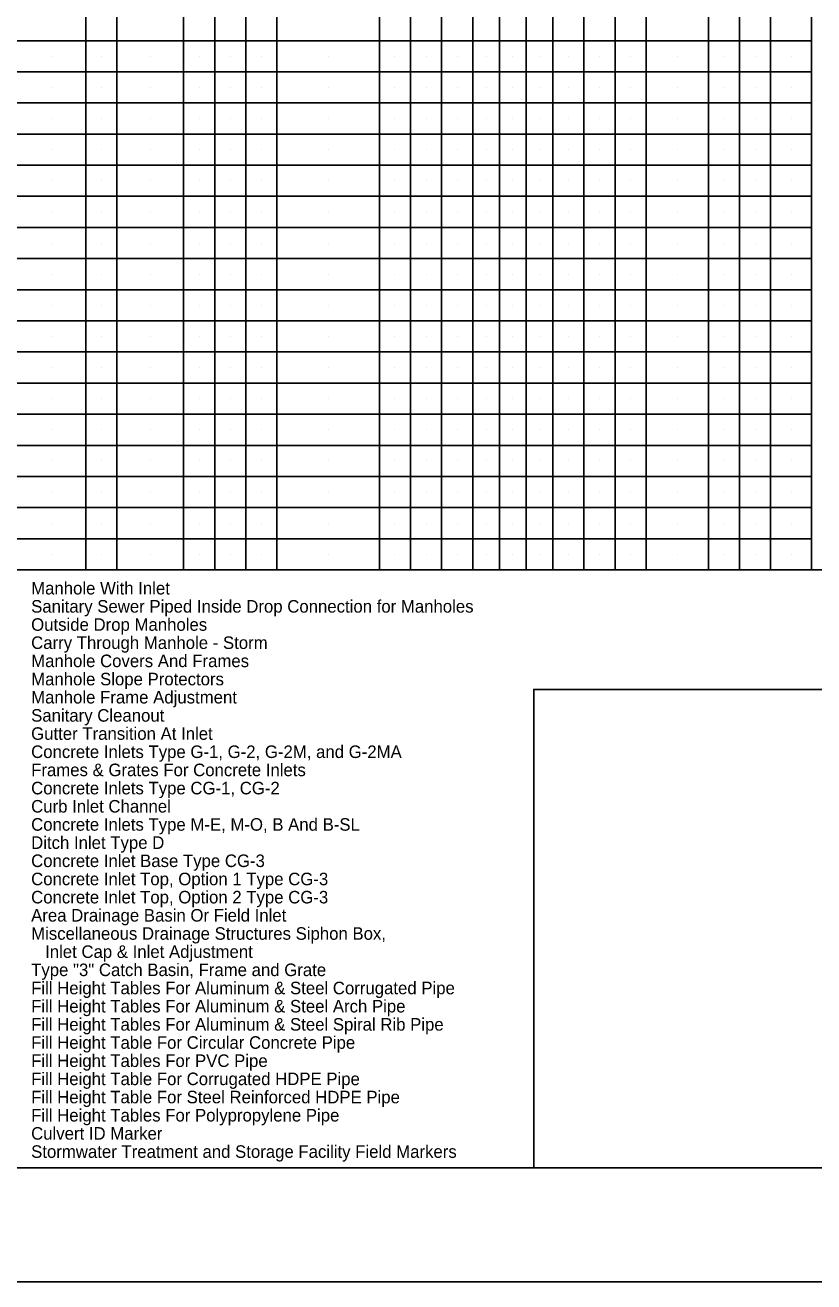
# Model space of a CAD drawing. Extents: x 0 to 1.42, y 0 to 0.92.
# Drawn here: x 0.7723 to 1.0608, y 0 to 0.4596 of the extents above; entities that cross this region are included whole.
import ezdxf

# ---------------------------------------------------------------- set-up
doc = ezdxf.new("R2010")
doc.units = 0
for name, color, linetype in [('#plot_shape', 7, 'Continuous'), ('P_ODOT_PLAN_Border', 7, 'Continuous'), ('P_ODOT_PLAN_General', 7, 'Continuous'), ('P_RDWY_PLAN_NotesTx', 7, 'Continuous')]:
    doc.layers.add(name, color=color, linetype=linetype)

msp = doc.modelspace()

# ---------------------------------------------------------------- linework, layer by layer
at = {"layer": '#plot_shape'}
msp.add_lwpolyline([(0, 0), (1.41667, 0), (1.41667, 0.91667), (0, 0.91667)], close=True, dxfattribs=at)
at = {"layer": 'P_ODOT_PLAN_Border'}
msp.add_lwpolyline([(0.0625, 0.04167), (1.39583, 0.04167), (1.39583, 0.875), (0.0625, 0.875)], close=True, dxfattribs=at)
msp.add_lwpolyline([(1.39587, 0.21667), (0.95837, 0.21667), (0.95837, 0.04167)], dxfattribs=at)
at = {"layer": 'P_ODOT_PLAN_General'}
for p, q in [((1.06002, 0.26037), (1.06002, 0.875)), ((0.93608, 0.26037), (0.93608, 0.86362)), ((0.96534, 0.26037), (0.96534, 0.86362)), ((0.97673, 0.26037), (0.97673, 0.85305)), ((0.98811, 0.26037), (0.98811, 0.85305)), ((0.99949, 0.26037), (0.99949, 0.85305)), ((1.02226, 0.26037), (1.02226, 0.85305)), ((1.03364, 0.26037), (1.03364, 0.85305)), ((1.04502, 0.26037), (1.04502, 0.85305)), ((0.86443, 0.26037), (0.86443, 0.83191)), ((0.94583, 0.26037), (0.94583, 0.82887)), ((0.95559, 0.26037), (0.95559, 0.82887)), ((0.80589, 0.26037), (0.80589, 0.82134)), ((0.84167, 0.26037), (0.84167, 0.82134)), ((0.90193, 0.26037), (0.90193, 0.82134)), ((0.91331, 0.26037), (0.91331, 0.82134)), ((0.79451, 0.26037), (0.79451, 0.81159)), ((0.83028, 0.26037), (0.83028, 0.81159)), ((0.85305, 0.26037), (0.85305, 0.81159)), ((0.92469, 0.26037), (0.92469, 0.81159)), ((1.06002, 0.45387), (0.55518, 0.45387)), ((0.78232, 0.44818), (0.78232, 0.44818)), ((0.8002, 0.44818), (0.8002, 0.44818)), ((0.81809, 0.44818), (0.81809, 0.44818)), ((0.83597, 0.44818), (0.83597, 0.44818)), ((0.84736, 0.44818), (0.84736, 0.44818)), ((0.85874, 0.44818), (0.85874, 0.44818)), ((0.88318, 0.44818), (0.88318, 0.44818)), ((0.90762, 0.44818), (0.90762, 0.44818)), ((0.919, 0.44818), (0.919, 0.44818)), ((0.93038, 0.44818), (0.93038, 0.44818)), ((0.94095, 0.44818), (0.94095, 0.44818)), ((0.95071, 0.44818), (0.95071, 0.44818)), ((0.96047, 0.44818), (0.96047, 0.44818)), ((0.97103, 0.44818), (0.97103, 0.44818)), ((0.98242, 0.44818), (0.98242, 0.44818)), ((0.9938, 0.44818), (0.9938, 0.44818)), ((1.01087, 0.44818), (1.01087, 0.44818)), ((1.02795, 0.44818), (1.02795, 0.44818)), ((1.03933, 0.44818), (1.03933, 0.44818)), ((1.05252, 0.44818), (1.05252, 0.44818)), ((1.06002, 0.44248), (0.55518, 0.44248)), ((0.78232, 0.43679), (0.78232, 0.43679)), ((0.8002, 0.43679), (0.8002, 0.43679)), ((0.81809, 0.43679), (0.81809, 0.43679)), ((0.83597, 0.43679), (0.83597, 0.43679)), ((0.84736, 0.43679), (0.84736, 0.43679)), ((0.85874, 0.43679), (0.85874, 0.43679)), ((0.88318, 0.43679), (0.88318, 0.43679)), ((0.90762, 0.43679), (0.90762, 0.43679)), ((0.919, 0.43679), (0.919, 0.43679)), ((0.93038, 0.43679), (0.93038, 0.43679)), ((0.94095, 0.43679), (0.94095, 0.43679)), ((0.95071, 0.43679), (0.95071, 0.43679)), ((0.96047, 0.43679), (0.96047, 0.43679)), ((0.97103, 0.43679), (0.97103, 0.43679)), ((0.98242, 0.43679), (0.98242, 0.43679)), ((0.9938, 0.43679), (0.9938, 0.43679)), ((1.01087, 0.43679), (1.01087, 0.43679)), ((1.02795, 0.43679), (1.02795, 0.43679)), ((1.03933, 0.43679), (1.03933, 0.43679)), ((1.05252, 0.43679), (1.05252, 0.43679)), ((1.06002, 0.4311), (0.55518, 0.4311)), ((0.78232, 0.42541), (0.78232, 0.42541)), ((0.8002, 0.42541), (0.8002, 0.42541)), ((0.81809, 0.42541), (0.81809, 0.42541)), ((0.83597, 0.42541), (0.83597, 0.42541)), ((0.84736, 0.42541), (0.84736, 0.42541)), ((0.85874, 0.42541), (0.85874, 0.42541)), ((0.88318, 0.42541), (0.88318, 0.42541)), ((0.90762, 0.42541), (0.90762, 0.42541)), ((0.919, 0.42541), (0.919, 0.42541)), ((0.93038, 0.42541), (0.93038, 0.42541)), ((0.94095, 0.42541), (0.94095, 0.42541)), ((0.95071, 0.42541), (0.95071, 0.42541)), ((0.96047, 0.42541), (0.96047, 0.42541)), ((0.97103, 0.42541), (0.97103, 0.42541)), ((0.98242, 0.42541), (0.98242, 0.42541)), ((0.9938, 0.42541), (0.9938, 0.42541)), ((1.01087, 0.42541), (1.01087, 0.42541)), ((1.02795, 0.42541), (1.02795, 0.42541)), ((1.03933, 0.42541), (1.03933, 0.42541)), ((1.05252, 0.42541), (1.05252, 0.42541)), ((1.06002, 0.41972), (0.55518, 0.41972)), ((0.78232, 0.41403), (0.78232, 0.41403)), ((0.8002, 0.41403), (0.8002, 0.41403)), ((0.81809, 0.41403), (0.81809, 0.41403)), ((0.83597, 0.41403), (0.83597, 0.41403)), ((0.84736, 0.41403), (0.84736, 0.41403)), ((0.85874, 0.41403), (0.85874, 0.41403)), ((0.88318, 0.41403), (0.88318, 0.41403)), ((0.90762, 0.41403), (0.90762, 0.41403)), ((0.919, 0.41403), (0.919, 0.41403)), ((0.93038, 0.41403), (0.93038, 0.41403)), ((0.94095, 0.41403), (0.94095, 0.41403)), ((0.95071, 0.41403), (0.95071, 0.41403)), ((0.96047, 0.41403), (0.96047, 0.41403)), ((0.97103, 0.41403), (0.97103, 0.41403)), ((0.98242, 0.41403), (0.98242, 0.41403)), ((0.9938, 0.41403), (0.9938, 0.41403)), ((1.01087, 0.41403), (1.01087, 0.41403)), ((1.02795, 0.41403), (1.02795, 0.41403)), ((1.03933, 0.41403), (1.03933, 0.41403)), ((1.05252, 0.41403), (1.05252, 0.41403)), ((1.06002, 0.40834), (0.55518, 0.40834)), ((0.78232, 0.40265), (0.78232, 0.40265)), ((0.8002, 0.40265), (0.8002, 0.40265)), ((0.81809, 0.40265), (0.81809, 0.40265)), ((0.83597, 0.40265), (0.83597, 0.40265)), ((0.84736, 0.40265), (0.84736, 0.40265)), ((0.85874, 0.40265), (0.85874, 0.40265)), ((0.88318, 0.40265), (0.88318, 0.40265)), ((0.90762, 0.40265), (0.90762, 0.40265)), ((0.919, 0.40265), (0.919, 0.40265)), ((0.93038, 0.40265), (0.93038, 0.40265)), ((0.94095, 0.40265), (0.94095, 0.40265)), ((0.95071, 0.40265), (0.95071, 0.40265)), ((0.96047, 0.40265), (0.96047, 0.40265)), ((0.97103, 0.40265), (0.97103, 0.40265)), ((0.98242, 0.40265), (0.98242, 0.40265)), ((0.9938, 0.40265), (0.9938, 0.40265)), ((1.01087, 0.40265), (1.01087, 0.40265)), ((1.02795, 0.40265), (1.02795, 0.40265)), ((1.03933, 0.40265), (1.03933, 0.40265)), ((1.05252, 0.40265), (1.05252, 0.40265)), ((1.06002, 0.39696), (0.55518, 0.39696)), ((0.78232, 0.39127), (0.78232, 0.39127)), ((0.8002, 0.39127), (0.8002, 0.39127)), ((0.81809, 0.39127), (0.81809, 0.39127)), ((0.83597, 0.39127), (0.83597, 0.39127)), ((0.84736, 0.39127), (0.84736, 0.39127)), ((0.85874, 0.39127), (0.85874, 0.39127)), ((0.88318, 0.39127), (0.88318, 0.39127)), ((0.90762, 0.39127), (0.90762, 0.39127)), ((0.919, 0.39127), (0.919, 0.39127)), ((0.93038, 0.39127), (0.93038, 0.39127)), ((0.94095, 0.39127), (0.94095, 0.39127)), ((0.95071, 0.39127), (0.95071, 0.39127)), ((0.96047, 0.39127), (0.96047, 0.39127)), ((0.97103, 0.39127), (0.97103, 0.39127)), ((0.98242, 0.39127), (0.98242, 0.39127)), ((0.9938, 0.39127), (0.9938, 0.39127)), ((1.01087, 0.39127), (1.01087, 0.39127)), ((1.02795, 0.39127), (1.02795, 0.39127)), ((1.03933, 0.39127), (1.03933, 0.39127)), ((1.05252, 0.39127), (1.05252, 0.39127)), ((1.06002, 0.38557), (0.55518, 0.38557)), ((0.78232, 0.37988), (0.78232, 0.37988)), ((0.8002, 0.37988), (0.8002, 0.37988)), ((0.81809, 0.37988), (0.81809, 0.37988)), ((0.83597, 0.37988), (0.83597, 0.37988)), ((0.84736, 0.37988), (0.84736, 0.37988)), ((0.85874, 0.37988), (0.85874, 0.37988)), ((0.88318, 0.37988), (0.88318, 0.37988)), ((0.90762, 0.37988), (0.90762, 0.37988)), ((0.919, 0.37988), (0.919, 0.37988)), ((0.93038, 0.37988), (0.93038, 0.37988)), ((0.94095, 0.37988), (0.94095, 0.37988)), ((0.95071, 0.37988), (0.95071, 0.37988)), ((0.96047, 0.37988), (0.96047, 0.37988)), ((0.97103, 0.37988), (0.97103, 0.37988)), ((0.98242, 0.37988), (0.98242, 0.37988)), ((0.9938, 0.37988), (0.9938, 0.37988)), ((1.01087, 0.37988), (1.01087, 0.37988)), ((1.02795, 0.37988), (1.02795, 0.37988)), ((1.03933, 0.37988), (1.03933, 0.37988)), ((1.05252, 0.37988), (1.05252, 0.37988)), ((1.06002, 0.37419), (0.55518, 0.37419)), ((0.78232, 0.3685), (0.78232, 0.3685)), ((0.8002, 0.3685), (0.8002, 0.3685)), ((0.81809, 0.3685), (0.81809, 0.3685)), ((0.83597, 0.3685), (0.83597, 0.3685)), ((0.84736, 0.3685), (0.84736, 0.3685)), ((0.85874, 0.3685), (0.85874, 0.3685)), ((0.88318, 0.3685), (0.88318, 0.3685)), ((0.90762, 0.3685), (0.90762, 0.3685)), ((0.919, 0.3685), (0.919, 0.3685)), ((0.93038, 0.3685), (0.93038, 0.3685)), ((0.94095, 0.3685), (0.94095, 0.3685)), ((0.95071, 0.3685), (0.95071, 0.3685)), ((0.96047, 0.3685), (0.96047, 0.3685)), ((0.97103, 0.3685), (0.97103, 0.3685)), ((0.98242, 0.3685), (0.98242, 0.3685)), ((0.9938, 0.3685), (0.9938, 0.3685)), ((1.01087, 0.3685), (1.01087, 0.3685)), ((1.02795, 0.3685), (1.02795, 0.3685)), ((1.03933, 0.3685), (1.03933, 0.3685)), ((1.05252, 0.3685), (1.05252, 0.3685)), ((1.06002, 0.36281), (0.55518, 0.36281)), ((0.78232, 0.35712), (0.78232, 0.35712)), ((0.8002, 0.35712), (0.8002, 0.35712)), ((0.81809, 0.35712), (0.81809, 0.35712)), ((0.83597, 0.35712), (0.83597, 0.35712)), ((0.84736, 0.35712), (0.84736, 0.35712)), ((0.85874, 0.35712), (0.85874, 0.35712)), ((0.88318, 0.35712), (0.88318, 0.35712)), ((0.90762, 0.35712), (0.90762, 0.35712)), ((0.919, 0.35712), (0.919, 0.35712)), ((0.93038, 0.35712), (0.93038, 0.35712)), ((0.94095, 0.35712), (0.94095, 0.35712)), ((0.95071, 0.35712), (0.95071, 0.35712)), ((0.96047, 0.35712), (0.96047, 0.35712)), ((0.97103, 0.35712), (0.97103, 0.35712)), ((0.98242, 0.35712), (0.98242, 0.35712)), ((0.9938, 0.35712), (0.9938, 0.35712)), ((1.01087, 0.35712), (1.01087, 0.35712)), ((1.02795, 0.35712), (1.02795, 0.35712)), ((1.03933, 0.35712), (1.03933, 0.35712)), ((1.05252, 0.35712), (1.05252, 0.35712)), ((1.06002, 0.35143), (0.55518, 0.35143)), ((0.78232, 0.34574), (0.78232, 0.34574)), ((0.8002, 0.34574), (0.8002, 0.34574)), ((0.81809, 0.34574), (0.81809, 0.34574)), ((0.83597, 0.34574), (0.83597, 0.34574)), ((0.84736, 0.34574), (0.84736, 0.34574)), ((0.85874, 0.34574), (0.85874, 0.34574)), ((0.88318, 0.34574), (0.88318, 0.34574)), ((0.90762, 0.34574), (0.90762, 0.34574)), ((0.919, 0.34574), (0.919, 0.34574)), ((0.93038, 0.34574), (0.93038, 0.34574)), ((0.94095, 0.34574), (0.94095, 0.34574)), ((0.95071, 0.34574), (0.95071, 0.34574)), ((0.96047, 0.34574), (0.96047, 0.34574)), ((0.97103, 0.34574), (0.97103, 0.34574)), ((0.98242, 0.34574), (0.98242, 0.34574)), ((0.9938, 0.34574), (0.9938, 0.34574)), ((1.01087, 0.34574), (1.01087, 0.34574)), ((1.02795, 0.34574), (1.02795, 0.34574)), ((1.03933, 0.34574), (1.03933, 0.34574)), ((1.05252, 0.34574), (1.05252, 0.34574)), ((1.06002, 0.34005), (0.55518, 0.34005)), ((0.78232, 0.33436), (0.78232, 0.33436)), ((0.8002, 0.33436), (0.8002, 0.33436)), ((0.81809, 0.33436), (0.81809, 0.33436)), ((0.83597, 0.33436), (0.83597, 0.33436)), ((0.84736, 0.33436), (0.84736, 0.33436)), ((0.85874, 0.33436), (0.85874, 0.33436)), ((0.88318, 0.33436), (0.88318, 0.33436)), ((0.90762, 0.33436), (0.90762, 0.33436)), ((0.919, 0.33436), (0.919, 0.33436)), ((0.93038, 0.33436), (0.93038, 0.33436)), ((0.94095, 0.33436), (0.94095, 0.33436)), ((0.95071, 0.33436), (0.95071, 0.33436)), ((0.96047, 0.33436), (0.96047, 0.33436)), ((0.97103, 0.33436), (0.97103, 0.33436)), ((0.98242, 0.33436), (0.98242, 0.33436)), ((0.9938, 0.33436), (0.9938, 0.33436)), ((1.01087, 0.33436), (1.01087, 0.33436)), ((1.02795, 0.33436), (1.02795, 0.33436)), ((1.03933, 0.33436), (1.03933, 0.33436)), ((1.05252, 0.33436), (1.05252, 0.33436)), ((1.06002, 0.32866), (0.55518, 0.32866)), ((0.78232, 0.32297), (0.78232, 0.32297)), ((0.8002, 0.32297), (0.8002, 0.32297)), ((0.81809, 0.32297), (0.81809, 0.32297)), ((0.83597, 0.32297), (0.83597, 0.32297)), ((0.84736, 0.32297), (0.84736, 0.32297)), ((0.85874, 0.32297), (0.85874, 0.32297)), ((0.88318, 0.32297), (0.88318, 0.32297)), ((0.90762, 0.32297), (0.90762, 0.32297)), ((0.919, 0.32297), (0.919, 0.32297)), ((0.93038, 0.32297), (0.93038, 0.32297)), ((0.94095, 0.32297), (0.94095, 0.32297)), ((0.95071, 0.32297), (0.95071, 0.32297)), ((0.96047, 0.32297), (0.96047, 0.32297)), ((0.97103, 0.32297), (0.97103, 0.32297)), ((0.98242, 0.32297), (0.98242, 0.32297)), ((0.9938, 0.32297), (0.9938, 0.32297)), ((1.01087, 0.32297), (1.01087, 0.32297)), ((1.02795, 0.32297), (1.02795, 0.32297)), ((1.03933, 0.32297), (1.03933, 0.32297)), ((1.05252, 0.32297), (1.05252, 0.32297)), ((1.06002, 0.31728), (0.55518, 0.31728)), ((0.78232, 0.31159), (0.78232, 0.31159)), ((0.8002, 0.31159), (0.8002, 0.31159)), ((0.81809, 0.31159), (0.81809, 0.31159)), ((0.83597, 0.31159), (0.83597, 0.31159)), ((0.84736, 0.31159), (0.84736, 0.31159)), ((0.85874, 0.31159), (0.85874, 0.31159)), ((0.88318, 0.31159), (0.88318, 0.31159)), ((0.90762, 0.31159), (0.90762, 0.31159)), ((0.919, 0.31159), (0.919, 0.31159)), ((0.93038, 0.31159), (0.93038, 0.31159)), ((0.94095, 0.31159), (0.94095, 0.31159)), ((0.95071, 0.31159), (0.95071, 0.31159)), ((0.96047, 0.31159), (0.96047, 0.31159)), ((0.97103, 0.31159), (0.97103, 0.31159)), ((0.98242, 0.31159), (0.98242, 0.31159)), ((0.9938, 0.31159), (0.9938, 0.31159)), ((1.01087, 0.31159), (1.01087, 0.31159)), ((1.02795, 0.31159), (1.02795, 0.31159)), ((1.03933, 0.31159), (1.03933, 0.31159)), ((1.05252, 0.31159), (1.05252, 0.31159)), ((1.06002, 0.3059), (0.55518, 0.3059)), ((0.78232, 0.30021), (0.78232, 0.30021)), ((0.8002, 0.30021), (0.8002, 0.30021)), ((0.81809, 0.30021), (0.81809, 0.30021)), ((0.83597, 0.30021), (0.83597, 0.30021)), ((0.84736, 0.30021), (0.84736, 0.30021)), ((0.85874, 0.30021), (0.85874, 0.30021)), ((0.88318, 0.30021), (0.88318, 0.30021)), ((0.90762, 0.30021), (0.90762, 0.30021)), ((0.919, 0.30021), (0.919, 0.30021)), ((0.93038, 0.30021), (0.93038, 0.30021)), ((0.94095, 0.30021), (0.94095, 0.30021)), ((0.95071, 0.30021), (0.95071, 0.30021)), ((0.96047, 0.30021), (0.96047, 0.30021)), ((0.97103, 0.30021), (0.97103, 0.30021)), ((0.98242, 0.30021), (0.98242, 0.30021)), ((0.9938, 0.30021), (0.9938, 0.30021)), ((1.01087, 0.30021), (1.01087, 0.30021)), ((1.02795, 0.30021), (1.02795, 0.30021)), ((1.03933, 0.30021), (1.03933, 0.30021)), ((1.05252, 0.30021), (1.05252, 0.30021)), ((1.06002, 0.29452), (0.55518, 0.29452)), ((0.78232, 0.28883), (0.78232, 0.28883)), ((0.8002, 0.28883), (0.8002, 0.28883)), ((0.81809, 0.28883), (0.81809, 0.28883)), ((0.83597, 0.28883), (0.83597, 0.28883)), ((0.84736, 0.28883), (0.84736, 0.28883)), ((0.85874, 0.28883), (0.85874, 0.28883)), ((0.88318, 0.28883), (0.88318, 0.28883)), ((0.90762, 0.28883), (0.90762, 0.28883)), ((0.919, 0.28883), (0.919, 0.28883)), ((0.93038, 0.28883), (0.93038, 0.28883)), ((0.94095, 0.28883), (0.94095, 0.28883)), ((0.95071, 0.28883), (0.95071, 0.28883)), ((0.96047, 0.28883), (0.96047, 0.28883)), ((0.97103, 0.28883), (0.97103, 0.28883)), ((0.98242, 0.28883), (0.98242, 0.28883)), ((0.9938, 0.28883), (0.9938, 0.28883)), ((1.01087, 0.28883), (1.01087, 0.28883)), ((1.02795, 0.28883), (1.02795, 0.28883)), ((1.03933, 0.28883), (1.03933, 0.28883)), ((1.05252, 0.28883), (1.05252, 0.28883)), ((1.06002, 0.28314), (0.55518, 0.28314)), ((0.78232, 0.27745), (0.78232, 0.27745)), ((0.8002, 0.27745), (0.8002, 0.27745)), ((0.81809, 0.27745), (0.81809, 0.27745)), ((0.83597, 0.27745), (0.83597, 0.27745)), ((0.84736, 0.27745), (0.84736, 0.27745)), ((0.85874, 0.27745), (0.85874, 0.27745)), ((0.88318, 0.27745), (0.88318, 0.27745)), ((0.90762, 0.27745), (0.90762, 0.27745)), ((0.919, 0.27745), (0.919, 0.27745)), ((0.93038, 0.27745), (0.93038, 0.27745)), ((0.94095, 0.27745), (0.94095, 0.27745)), ((0.95071, 0.27745), (0.95071, 0.27745)), ((0.96047, 0.27745), (0.96047, 0.27745)), ((0.97103, 0.27745), (0.97103, 0.27745)), ((0.98242, 0.27745), (0.98242, 0.27745)), ((0.9938, 0.27745), (0.9938, 0.27745)), ((1.01087, 0.27745), (1.01087, 0.27745)), ((1.02795, 0.27745), (1.02795, 0.27745)), ((1.03933, 0.27745), (1.03933, 0.27745)), ((1.05252, 0.27745), (1.05252, 0.27745)), ((1.06002, 0.27175), (0.55518, 0.27175)), ((0.78232, 0.26606), (0.78232, 0.26606)), ((0.8002, 0.26606), (0.8002, 0.26606)), ((0.81809, 0.26606), (0.81809, 0.26606)), ((0.83597, 0.26606), (0.83597, 0.26606)), ((0.84736, 0.26606), (0.84736, 0.26606)), ((0.85874, 0.26606), (0.85874, 0.26606)), ((0.88318, 0.26606), (0.88318, 0.26606)), ((0.90762, 0.26606), (0.90762, 0.26606)), ((0.919, 0.26606), (0.919, 0.26606)), ((0.93038, 0.26606), (0.93038, 0.26606)), ((0.94095, 0.26606), (0.94095, 0.26606)), ((0.95071, 0.26606), (0.95071, 0.26606)), ((0.96047, 0.26606), (0.96047, 0.26606)), ((0.97103, 0.26606), (0.97103, 0.26606)), ((0.98242, 0.26606), (0.98242, 0.26606)), ((0.9938, 0.26606), (0.9938, 0.26606)), ((1.01087, 0.26606), (1.01087, 0.26606)), ((1.02795, 0.26606), (1.02795, 0.26606)), ((1.03933, 0.26606), (1.03933, 0.26606)), ((1.05252, 0.26606), (1.05252, 0.26606)), ((1.39582, 0.26037), (0.0625, 0.26037)), ((1.39582, 0.26037), (0.0625, 0.26037))]:
    msp.add_line(p, q, dxfattribs=at)

# ---------------------------------------------------------------- texts
at = {"layer": 'P_RDWY_PLAN_NotesTx'}
for s, p in [('Manhole With Inlet', (0.77453, 0.25137)), ('Sanitary Sewer Piped Inside Drop Connection for Manholes', (0.77453, 0.24473)), ('Outside Drop Manholes', (0.77453, 0.23808)), ('Carry Through Manhole - Storm', (0.77453, 0.23144)), ('Manhole Covers And Frames', (0.77453, 0.22479)), ('Manhole Slope Protectors', (0.77453, 0.21814)), ('Manhole Frame Adjustment', (0.77453, 0.2115)), ('Sanitary Cleanout', (0.77453, 0.20485)), ('Gutter Transition At Inlet', (0.77453, 0.19821)), ('Concrete Inlets Type G-1, G-2, G-2M, and G-2MA', (0.77453, 0.19156)), ('Frames & Grates For Concrete Inlets', (0.77453, 0.18492)), ('Concrete Inlets Type CG-1, CG-2', (0.77453, 0.17827)), ('Curb Inlet Channel', (0.77453, 0.17162)), ('Concrete Inlets Type M-E, M-O, B And B-SL', (0.77453, 0.16498)), ('Ditch Inlet Type D', (0.77453, 0.15833)), ('Concrete Inlet Base Type CG-3', (0.77453, 0.15169)), ('Concrete Inlet Top, Option 1 Type CG-3', (0.77453, 0.14504)), ('Concrete Inlet Top, Option 2 Type CG-3', (0.77453, 0.13839)), ('Area Drainage Basin Or Field Inlet', (0.77453, 0.13175)), ('Miscellaneous Drainage Structures Siphon Box,', (0.77453, 0.1251)), ('   Inlet Cap & Inlet Adjustment', (0.77453, 0.11846)), ('Type "3" Catch Basin, Frame and Grate', (0.77453, 0.11181)), ('Fill Height Tables For Aluminum & Steel Corrugated Pipe', (0.77453, 0.10517)), ('Fill Height Tables For Aluminum & Steel Arch Pipe', (0.77453, 0.09852)), ('Fill Height Tables For Aluminum & Steel Spiral Rib Pipe ', (0.77453, 0.09187)), ('Fill Height Table For Circular Concrete Pipe', (0.77453, 0.08523)), ('Fill Height Tables For PVC Pipe ', (0.77453, 0.07858)), ('Fill Height Table For Corrugated HDPE Pipe', (0.77453, 0.07194)), ('Fill Height Table For Steel Reinforced HDPE Pipe', (0.77453, 0.06529)), ('Fill Height Tables For Polypropylene Pipe', (0.77453, 0.05864)), ('Culvert ID Marker', (0.77453, 0.052)), ('Stormwater Treatment and Storage Facility Field Markers', (0.77453, 0.04535))]:
    msp.add_text(s, height=0.0045833, dxfattribs=at).set_placement(p)

doc.saveas('drawing.dxf')
